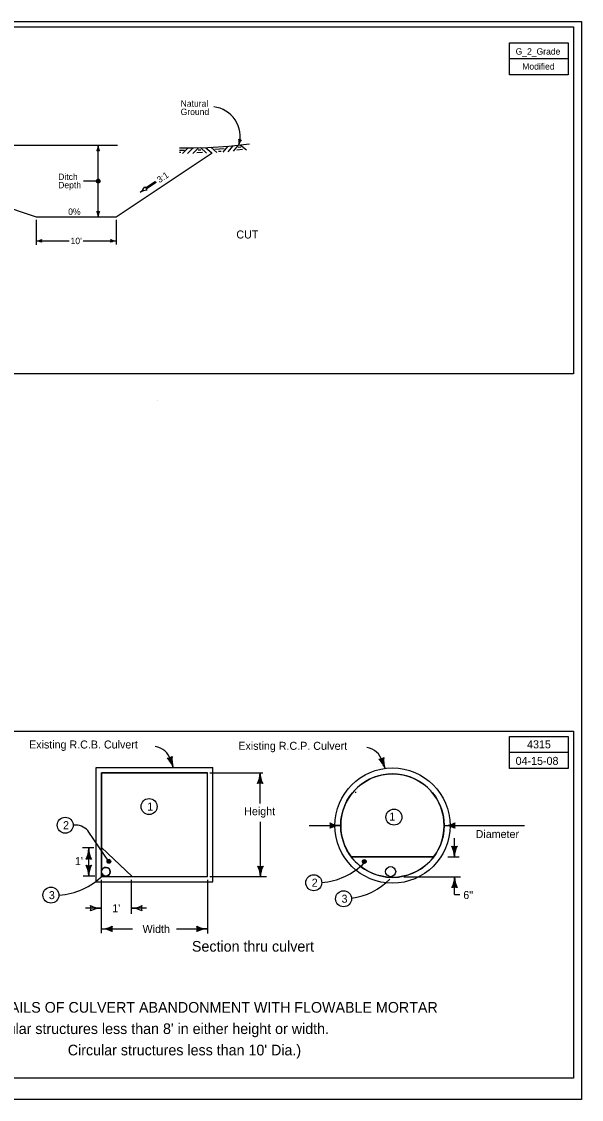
# Model space of a CAD drawing. Extents: x 10133 to 81668, y 7924 to 11018.
# Drawn here: x 12218 to 13268, y 7924 to 9944 of the extents above; entities that cross this region are included whole.
import ezdxf

# ---------------------------------------------------------------- set-up
doc = ezdxf.new("R2010")
doc.units = 0
for name, color, linetype in [('dsnCellElements', 7, 'Continuous'), ('DsnShtMinorGrid06', 7, 'Continuous'), ('DsnShtMinorGrid08', 7, 'Continuous'), ('DsnShtMinorGrid09', 7, 'Continuous'), ('DsnShtMinorGrid10', 7, 'Continuous'), ('DsnShtMinorGrid11', 7, 'Continuous'), ('dsnStdNameDate', 7, 'Continuous'), ('Level 12', 7, 'Continuous'), ('SheetBorder', 7, 'Continuous'), ('ShtPlotIdentification', 7, 'Continuous')]:
    doc.layers.add(name, color=color, linetype=linetype)

msp = doc.modelspace()

# ---------------------------------------------------------------- linework, layer by layer
at = {"layer": 'dsnCellElements'}
for p, q in [((12357.4, 8331.9), (12357.4, 8546.4)), ((12357.4, 8546.4), (12576.1, 8546.4)), ((12502.1, 8546.4), (12495.6, 8564.5)), ((12576.1, 8331.9), (12576.1, 8546.4)), ((12899.2, 8544.3), (12892.6, 8562.4)), ((12367.5, 8342), (12367.5, 8536.3)), ((12367.5, 8536.3), (12566, 8536.3)), ((12566, 8342), (12566, 8536.3)), ((12570.5, 8536), (12670.1, 8536)), ((12664.9, 8478.4), (12664.9, 8536)), ((12664.9, 8536), (12664.9, 8516.8)), ((12665.5, 8341.7), (12665.5, 8444)), ((12319.2, 8438), (12314.4, 8438)), ((12381.3, 8370.2), (12344, 8424.9)), ((12757.2, 8437.2), (12816.1, 8437.2)), ((12816.1, 8437.2), (12796.9, 8437.2)), ((13010.1, 8437.2), (13160.6, 8437.2)), ((13010.1, 8437.2), (13029.3, 8437.2)), ((13029.5, 8378.1), (13029.5, 8413.7)), ((12332.1, 8396.1), (12353.2, 8396.1)), ((12343.7, 8394), (12343.7, 8374.8)), ((12343.7, 8342.9), (12343.7, 8394)), ((12367.5, 8395.9), (12424.7, 8342)), ((13029.4, 8378.6), (13029.4, 8397.8)), ((12836, 8378.4), (12984.5, 8378.4)), ((13016.9, 8378.4), (13038, 8378.4)), ((12333.2, 8342.9), (12354.7, 8342.9)), ((12343.7, 8342.9), (12343.7, 8362.1)), ((12665.6, 8341.3), (12665.6, 8360.5)), ((12357.4, 8331.9), (12576.1, 8331.9)), ((12367.5, 8342), (12566, 8342)), ((12367.5, 8235.9), (12367.5, 8335.8)), ((12423.8, 8271.6), (12423.8, 8335.8)), ((12566.8, 8234.9), (12566.8, 8335.8)), ((12570.5, 8341.6), (12676.9, 8341.6)), ((12934.4, 8341.2), (13040.9, 8341.2)), ((13029.5, 8307.8), (13029.5, 8341.2)), ((13029.6, 8340.9), (13029.6, 8321.7)), ((13029.5, 8307.8), (13039.5, 8307.8)), ((12367.3, 8282.2), (12337.4, 8282.2)), ((12452, 8282.2), (12423.3, 8282.2)), ((12367.5, 8243.6), (12386.7, 8243.6)), ((12367.5, 8243.6), (12425.5, 8243.6)), ((12508.4, 8243.6), (12566.5, 8243.6)), ((12566.5, 8243.6), (12547.3, 8243.6))]:
    msp.add_line(p, q, dxfattribs=at)
for points in [[(12499, 8565.3), (12495.9, 8563.4), (12492.3, 8562.9), (12495.7, 8559.5), (12499.5, 8553.7), (12498.6, 8561.1), (12498.8, 8564.6), (12496.2, 8562.8), (12493.9, 8562.3), (12496.1, 8560.1), (12498.3, 8556.9), (12498, 8561), (12498, 8563.3), (12495.2, 8561.8), (12497.3, 8559.6), (12497.2, 8561.9), (12496.2, 8561.6), (12496.9, 8560.7)], [(12896.1, 8563.2), (12893, 8561.3), (12889.4, 8560.8), (12892.8, 8557.5), (12896.5, 8551.6), (12895.6, 8559), (12895.9, 8562.5), (12893.2, 8560.7), (12890.9, 8560.2), (12893.2, 8558), (12895.4, 8554.8), (12895.1, 8558.9), (12895.1, 8561.2), (12892.3, 8559.8), (12894.4, 8557.5), (12894.3, 8559.8), (12893.3, 8559.5), (12893.9, 8558.6)], [(12661.4, 8517.2), (12665, 8517.9), (12668.6, 8517.1), (12666.5, 8521.4), (12665, 8528.3), (12663.2, 8520.9), (12661.8, 8517.8), (12665, 8518.6), (12667.3, 8518.3), (12665.9, 8521.1), (12665, 8524.9), (12663.8, 8520.8), (12663.1, 8518.7), (12666.1, 8519.1), (12665, 8521.9), (12664.3, 8519.7), (12665.3, 8519.7), (12665, 8520.7)], [(12843, 8498.6), (12844.8, 8500.4)], [(12797.3, 8440.8), (12798, 8437.2), (12797.2, 8433.6), (12801.5, 8435.7), (12808.4, 8437.2), (12801, 8438.9), (12797.9, 8440.3), (12798.6, 8437.2), (12798.3, 8434.9), (12801.2, 8436.2), (12805, 8437.2), (12800.9, 8438.4), (12798.8, 8439.1), (12799.2, 8436), (12802, 8437.2), (12799.8, 8437.9), (12799.8, 8436.8), (12800.8, 8437.2)], [(13028.9, 8433.6), (13028.2, 8437.2), (13028.9, 8440.8), (13024.6, 8438.8), (13017.8, 8437.2), (13025.2, 8435.5), (13028.3, 8434.1), (13027.5, 8437.2), (13027.8, 8439.5), (13025, 8438.2), (13021.2, 8437.2), (13025.3, 8436), (13027.4, 8435.3), (13027, 8438.4), (13024.2, 8437.2), (13026.4, 8436.5), (13026.4, 8437.6), (13025.4, 8437.2)], [(12340.2, 8375.2), (12343.7, 8375.9), (12347.3, 8375.2), (12345.3, 8379.5), (12343.7, 8386.3), (12342, 8379), (12340.6, 8375.8), (12343.7, 8376.6), (12346, 8376.3), (12344.7, 8379.1), (12343.7, 8382.9), (12342.6, 8378.9), (12341.8, 8376.8), (12344.9, 8377.2), (12343.7, 8380), (12343, 8377.8), (12344.1, 8377.7), (12343.8, 8378.8)], [(13033, 8397.4), (13029.4, 8396.7), (13025.8, 8397.4), (13027.9, 8393.1), (13029.4, 8386.3), (13031.1, 8393.6), (13032.5, 8396.8), (13029.4, 8396), (13027.1, 8396.3), (13028.4, 8393.5), (13029.4, 8389.7), (13030.6, 8393.7), (13031.3, 8395.8), (13028.2, 8395.4), (13029.4, 8392.6), (13030.1, 8394.8), (13029, 8394.9), (13029.4, 8393.8)], [(12381.6, 8373.4), (12380.4, 8372.8), (12378.6, 8372.3), (12378.2, 8370.4), (12378.5, 8368.8), (12379.7, 8367.3), (12381.4, 8367.4), (12383.3, 8367.7), (12384.1, 8369.1), (12384.3, 8370.7), (12383.2, 8372.7), (12381.9, 8372.9), (12380, 8372.4), (12378.5, 8371.2), (12378.6, 8369.5), (12379.7, 8368.1), (12381.4, 8367.9), (12383.2, 8368.3), (12383.5, 8369.3), (12383.9, 8370.6), (12383, 8372.1), (12381.7, 8372.1), (12380.2, 8371.8), (12379, 8370.9), (12379.6, 8369.4), (12380.8, 8368.5), (12382.3, 8368.5), (12382.7, 8369.3), (12383.2, 8370.2), (12382.4, 8371.5), (12381.3, 8371.7), (12380.3, 8371.2), (12380.2, 8370.1), (12380.7, 8369.2), (12381.8, 8369), (12382.3, 8369.4), (12382.6, 8370), (12382, 8370.9), (12381.3, 8371.1), (12380.6, 8370.7), (12380.7, 8370.1), (12381.2, 8369.7), (12382, 8369.7), (12382, 8370.2), (12381.3, 8370.5)], [(12833, 8382.5), (12833, 8382.5)], [(12860.6, 8373), (12859.4, 8372.5), (12857.5, 8371.9), (12857.2, 8370), (12857.4, 8368.4), (12858.6, 8366.9), (12860.4, 8367), (12862.2, 8367.3), (12863.1, 8368.8), (12863.3, 8370.3), (12862.2, 8372.3), (12860.8, 8372.5), (12859, 8372), (12857.5, 8370.9), (12857.5, 8369.1), (12858.7, 8367.7), (12860.3, 8367.5), (12862.2, 8367.9), (12862.5, 8368.9), (12862.8, 8370.2), (12862, 8371.7), (12860.6, 8371.7), (12859.1, 8371.4), (12858, 8370.6), (12858.6, 8369), (12859.7, 8368.1), (12861.3, 8368.1), (12861.6, 8368.9), (12862.1, 8369.9), (12861.4, 8371.1), (12860.2, 8371.4), (12859.2, 8370.8), (12859.2, 8369.7), (12859.7, 8368.9), (12860.7, 8368.6), (12861.2, 8369), (12861.5, 8369.6), (12861, 8370.5), (12860.3, 8370.7), (12859.5, 8370.3), (12859.7, 8369.7), (12860.2, 8369.3), (12860.9, 8369.3), (12860.9, 8369.8), (12860.3, 8370.1)], [(12347.3, 8361.7), (12343.7, 8361), (12340.1, 8361.8), (12342.2, 8357.5), (12343.7, 8350.6), (12345.4, 8358), (12346.8, 8361.1), (12343.7, 8360.4), (12341.4, 8360.7), (12342.7, 8357.8), (12343.7, 8354), (12344.9, 8358.1), (12345.6, 8360.2), (12342.5, 8359.8), (12343.7, 8357), (12344.4, 8359.2), (12343.3, 8359.2), (12343.7, 8358.2)], [(12669.1, 8360.2), (12665.6, 8359.4), (12662, 8360.2), (12664, 8355.9), (12665.6, 8349.1), (12667.3, 8356.4), (12668.7, 8359.6), (12665.6, 8358.8), (12663.3, 8359.1), (12664.6, 8356.2), (12665.6, 8352.5), (12666.7, 8356.5), (12667.5, 8358.6), (12664.4, 8358.2), (12665.6, 8355.4), (12666.3, 8357.6), (12665.2, 8357.6), (12665.5, 8356.6)], [(13026, 8322.1), (13029.6, 8322.8), (13033.2, 8322), (13031.1, 8326.3), (13029.6, 8333.2), (13027.9, 8325.8), (13026.5, 8322.7), (13029.6, 8323.4), (13031.9, 8323.1), (13030.6, 8326), (13029.6, 8329.8), (13028.4, 8325.7), (13027.7, 8323.6), (13030.8, 8324), (13029.6, 8326.8), (13028.9, 8324.6), (13030, 8324.6), (13029.6, 8325.6)], [(12386.3, 8240), (12385.6, 8243.6), (12386.3, 8247.2), (12382, 8245.1), (12375.2, 8243.6), (12382.5, 8241.9), (12385.7, 8240.5), (12384.9, 8243.6), (12385.2, 8245.9), (12382.4, 8244.6), (12378.6, 8243.6), (12382.6, 8242.4), (12384.7, 8241.7), (12384.3, 8244.8), (12381.5, 8243.6), (12383.7, 8242.9), (12383.8, 8244), (12382.7, 8243.6)], [(12547.7, 8247.1), (12548.4, 8243.6), (12547.7, 8240), (12552, 8242), (12558.8, 8243.6), (12551.4, 8245.3), (12548.3, 8246.7), (12549.1, 8243.6), (12548.8, 8241.3), (12551.6, 8242.6), (12555.4, 8243.6), (12551.4, 8244.7), (12549.3, 8245.5), (12549.6, 8242.4), (12552.4, 8243.6), (12550.2, 8244.3), (12550.2, 8243.2), (12551.2, 8243.5)]]:
    msp.add_lwpolyline(points, dxfattribs=at)
for centre, radius in [((12913.1, 8437.2), 108), ((12913.1, 8437.2), 97), ((12456.7, 8472.9), 15), ((12915.9, 8453.1), 15), ((12299.4, 8438), 15), ((12381.3, 8370.2), 3.5), ((12860.3, 8369.8), 3.5), ((12375.6, 8350.7), 8.23), ((12765.6, 8330.2), 15), ((12909.7, 8350.9), 9.51), ((12272.7, 8306.9), 15), ((12821.5, 8300.1), 15)]:
    msp.add_circle(centre, radius, dxfattribs=at)
for centre, radius, start, end in [((12461.9, 8549.3), 36.9, 17.6823, 79.9899), ((12489.9, 8579.9), 16.4, 272.2666, 307.7334), ((12542.1, 8560.9), 42.5, 171.9275, 200), ((12858.9, 8547.2), 36.9, 17.6823, 79.9899), ((12462.2, 8531.9), 42.5, 20, 48.0725), ((12887, 8577.8), 16.4, 272.2666, 307.7334), ((12859.3, 8529.8), 42.5, 20, 48.0725), ((12939.1, 8558.8), 42.5, 171.9275, 200), ((12622.4, 8536), 42.5, 331.9275, 0), ((12707.4, 8536), 42.5, 180, 208.0725), ((12664.9, 8500.4), 16.4, 72.2666, 107.7334), ((12319.2, 8408), 30, 34.2688, 90), ((12780.5, 8437.2), 16.4, 342.2666, 17.7334), ((12816.1, 8479.7), 42.5, 241.9275, 270), ((12816.1, 8394.7), 42.5, 90, 118.0725), ((13010.1, 8479.7), 42.5, 270, 298.0725), ((13010.1, 8394.7), 42.5, 61.9275, 90), ((13045.7, 8437.2), 16.4, 162.2666, 197.7334), ((12301.2, 8394), 42.5, 331.9275, 0), ((12386.2, 8394), 42.5, 180, 208.0725), ((13029.4, 8414.2), 16.4, 252.2666, 287.7333), ((12986.9, 8378.6), 42.5, 0, 28.0725), ((13071.9, 8378.6), 42.5, 151.9275, 180), ((12343.7, 8358.4), 16.4, 72.2666, 107.7334), ((12343.7, 8378.5), 16.4, 252.2666, 287.7333), ((12301.2, 8342.9), 42.5, 0, 28.0725), ((12386.2, 8342.9), 42.5, 151.9275, 180), ((12769.6, 8458.8), 128.8, 274.9104, 314.6972), ((12279.4, 8435.5), 128.8, 273.6929, 314.6972), ((12665.6, 8377), 16.4, 252.2666, 287.7333), ((12623.1, 8341.3), 42.5, 0, 28.0725), ((12708.1, 8341.3), 42.5, 151.9275, 180), ((12817.9, 8428.4), 128.8, 278.3054, 314.6972), ((12987.1, 8340.9), 42.5, 331.9275, 0), ((13072.1, 8340.9), 42.5, 180, 208.0725), ((13029.6, 8305.3), 16.4, 72.2666, 107.7334), ((12331.5, 8282.2), 16.4, 342.2666, 17.7333), ((12367.1, 8324.7), 42.5, 241.9275, 270), ((12367.1, 8239.7), 42.5, 90, 118.0725), ((12423.3, 8324.7), 42.5, 270, 298.0725), ((12423.3, 8239.7), 42.5, 61.9275, 90), ((12458.9, 8282.2), 16.4, 162.2666, 197.7334), ((12367.5, 8286.1), 42.5, 270, 298.0725), ((12367.5, 8201.1), 42.5, 61.9275, 90), ((12403.1, 8243.6), 16.4, 162.2666, 197.7334), ((12530.9, 8243.6), 16.4, 342.2666, 17.7333), ((12566.5, 8286.1), 42.5, 241.9275, 270), ((12566.5, 8201.1), 42.5, 90, 118.0725)]:
    msp.add_arc(centre, radius, start, end, dxfattribs=at)
at = {"layer": 'DsnShtMinorGrid06'}
for p, q in [((12397.7, 9711.5), (11691.5, 9711.5)), ((12361.3, 9578.2), (12361.3, 9707.6)), ((12361.3, 9645), (12333.8, 9645)), ((12245, 9572.2), (12245, 9525.3)), ((12395, 9572.2), (12395, 9526.1)), ((12245, 9532.9), (12307, 9532.9)), ((12333, 9532.9), (12395, 9532.9))]:
    msp.add_line(p, q, dxfattribs=at)
msp.add_lwpolyline([(12361, 9641.8), (12362.2, 9642.3), (12364, 9642.9), (12364.4, 9644.8), (12364.1, 9646.4), (12363, 9647.9), (12361.2, 9647.8), (12359.4, 9647.5), (12358.5, 9646), (12358.3, 9644.5), (12359.4, 9642.5), (12360.7, 9642.3), (12362.6, 9642.8), (12364.1, 9643.9), (12364, 9645.7), (12362.9, 9647.1), (12361.2, 9647.2), (12359.4, 9646.9), (12359.1, 9645.8), (12358.7, 9644.6), (12359.6, 9643.1), (12360.9, 9643.1), (12362.5, 9643.4), (12363.6, 9644.2), (12363, 9645.7), (12361.9, 9646.6), (12360.3, 9646.7), (12359.9, 9645.9), (12359.4, 9644.9), (12360.2, 9643.7), (12361.3, 9643.4), (12362.3, 9644), (12362.4, 9645.1), (12361.9, 9645.9), (12360.8, 9646.2), (12360.3, 9645.8), (12360, 9645.1), (12360.6, 9644.2), (12361.3, 9644.1), (12362, 9644.5), (12361.9, 9645.1), (12361.4, 9645.5), (12360.7, 9645.5), (12360.7, 9645), (12361.3, 9644.7)], dxfattribs=at)
msp.add_circle((12361.3, 9645), 3.5, dxfattribs=at)
for centre, radius, start, end in [((12340, 9711.5), 21.3, 331.9275, 0), ((12361.3, 9693.7), 8.21, 72.2666, 107.7334), ((12382.5, 9711.5), 21.3, 180, 208.0725), ((12361.3, 9596), 8.21, 252.2666, 287.7334), ((12340, 9578.2), 21.3, 0, 28.0725), ((12382.5, 9578.2), 21.3, 151.9275, 180), ((12245, 9554.1), 21.3, 270, 298.0725), ((12262.8, 9532.9), 8.21, 162.2666, 197.7334), ((12377.2, 9532.9), 8.21, 342.2666, 17.7334), ((12395, 9554.1), 21.3, 241.9275, 270), ((12245, 9511.6), 21.3, 61.9275, 90), ((12395, 9511.6), 21.3, 90, 118.0725)]:
    msp.add_arc(centre, radius, start, end, dxfattribs=at)
at = {"layer": 'DsnShtMinorGrid08'}
for points in [[(10147.5, 9934), (13252.5, 9934), (13252.5, 9284), (10147.5, 9284), (10147.5, 9934)], [(13242.5, 9904), (13242.5, 9844), (13132.5, 9844), (13132.5, 9904), (13242.5, 9904), (13242.5, 9874), (13132.5, 9874)]]:
    msp.add_lwpolyline(points, dxfattribs=at)
at = {"layer": 'DsnShtMinorGrid09'}
for p, q in [((12450.1, 9632.2), (12468.4, 9644.4)), ((12469.7, 9642.4), (12451.4, 9630.2)), ((12468.4, 9644.4), (12469.7, 9642.4)), ((12440.1, 9624.1), (12440.1, 9624.1)), ((12448.5, 9634.5), (12450.1, 9632.2)), ((12451.4, 9630.2), (12452.9, 9627.9))]:
    msp.add_line(p, q, dxfattribs=at)
for centre, radius, start, end in [((12571.4, 9728.6), 56, 343.9435, 83.3835), ((12628.7, 9730.6), 8.21, 241.2344, 276.7011), ((12604.4, 9717.2), 21.3, 348.9677, 17.0402), ((12646.1, 9709), 21.3, 140.8953, 168.9677), ((12424.9, 9645), 25.8, 306.0394, 336.0695), ((12453.5, 9602.1), 25.8, 91.3054, 121.3354)]:
    msp.add_arc(centre, radius, start, end, dxfattribs=at)
at = {"layer": 'DsnShtMinorGrid10'}
for p, q in [((12395, 9578.2), (12574.7, 9698)), ((11977.5, 9667.4), (12245, 9578.2)), ((12245, 9578.2), (12395, 9578.2))]:
    msp.add_line(p, q, dxfattribs=at)
at = {"layer": 'DsnShtMinorGrid11'}
for p, q in [((12530.2, 9707.3), (12519.5, 9696.8)), ((12539.5, 9707.1), (12528.8, 9696.6)), ((12549.3, 9707.5), (12539, 9696.6)), ((12553.3, 9707.7), (12564.2, 9697.4)), ((12563.1, 9707.6), (12574.4, 9697.8)), ((12572.4, 9708.4), (12583.7, 9698.6)), ((12604.7, 9710.6), (12594.9, 9699.3)), ((12614, 9711.4), (12604.6, 9699.7)), ((12623.7, 9712.6), (12614.3, 9700.9)), ((12627.8, 9713.1), (12639.4, 9703.7))]:
    msp.add_line(p, q, dxfattribs=at)
for points in [[(12513.9, 9703.3), (12523, 9703.3)], [(12513.9, 9699), (12516.4, 9699)], [(12514, 9707.4), (12540.5, 9707.3), (12567, 9708.1), (12606.1, 9710.7), (12645, 9714.9)], [(12546.2, 9698.9), (12556.9, 9699.2)], [(12549, 9703.4), (12553.9, 9703.5)], [(12579.8, 9704.8), (12597.8, 9706)], [(12586.7, 9700.9), (12591.6, 9701.3)], [(12621.4, 9703.8), (12631.9, 9705)], [(12623.7, 9708.5), (12628.6, 9709)]]:
    msp.add_lwpolyline(points, dxfattribs=at)
at = {"layer": 'Level 12'}
for p, q in [((12990.2, 8378.4), (12836, 8378.4)), ((12836, 8378.4), (12990.2, 8378.4))]:
    msp.add_line(p, q, dxfattribs=at)
for points in [[(10147.5, 8614), (13252.5, 8614), (13252.5, 7964), (10147.5, 7964), (10147.5, 8614)], [(13242.5, 8604), (13242.5, 8544), (13132.5, 8544), (13132.5, 8604), (13242.5, 8604), (13242.5, 8574), (13132.5, 8574)], [(12367.5, 8349.5), (12367.5, 8342), (12424.7, 8342), (12367.5, 8395.9), (12367.5, 8351.9)]]:
    msp.add_lwpolyline(points, dxfattribs=at)
msp.add_lwpolyline([(12566, 8342), (12566, 8536.3), (12367.5, 8536.3), (12367.5, 8395.9), (12424.7, 8342)], close=True, dxfattribs=at)
for centre, radius in [((12456.7, 8472.9), 15), ((12915.9, 8453.1), 15), ((12381.3, 8370.2), 3.5), ((12860.3, 8369.8), 3.5), ((12909.7, 8350.9), 9.51)]:
    msp.add_circle(centre, radius, dxfattribs=at)
for centre, radius, start, end in [((12913.1, 8437.2), 97, 322.6702, 217.3298), ((12913.1, 8437.2), 97, 217.3298, 322.6702), ((12375.6, 8350.7), 8.23, 188.3205, 171.6795)]:
    msp.add_arc(centre, radius, start, end, dxfattribs=at)
at = {"layer": 'SheetBorder'}
msp.add_lwpolyline([(10132.5, 9944), (13267.5, 9944), (13267.5, 7924), (10132.5, 7924)], close=True, dxfattribs=at)
at = {"layer": 'ShtPlotIdentification'}
for p, q in [((12472.5, 9234), (12472.5, 9234)), ((13252.5, 8614), (13252.5, 8614)), ((12984.5, 8378.4), (12990.5, 8378.4))]:
    msp.add_line(p, q, dxfattribs=at)

# ---------------------------------------------------------------- texts
at = {"layer": 'DsnShtMinorGrid06'}
for s, p in [('Ditch', (12286.3, 9647.1)), ('Depth', (12286.3, 9631.6)), ('0%', (12305, 9581.7)), ("10'", (12309.5, 9526.9))]:
    msp.add_text(s, height=12, dxfattribs=at).set_placement(p)
at = {"layer": 'DsnShtMinorGrid09'}
for s, p in [('Ground', (12515.9, 9768.8)), ('Natural', (12515.9, 9784.4))]:
    msp.add_text(s, height=12, dxfattribs=at).set_placement(p)
for s, height, rotation, p in [('3:1', 12, 33.6874, (12476.3, 9641)), ('CUT', 15, 359.9585, (12620.4, 9537.5))]:
    msp.add_text(s, height=height, rotation=rotation, dxfattribs=at).set_placement(p)
at = {"layer": 'dsnStdNameDate'}
for s, height, p in [('G_2_Grade', 12, (13144.1, 9882)), ('Modified', 12, (13156.5, 9854)), ('4315', 15, (13165.6, 8582)), ('04-15-08', 15, (13144.1, 8551))]:
    msp.add_text(s, height=height, dxfattribs=at).set_placement(p)
at = {"layer": 'ShtPlotIdentification'}
for s, height, p in [('Existing R.C.B. Culvert', 15, (12231.6, 8581.7)), ('Existing R.C.P. Culvert', 15, (12624.1, 8579.2)), ('1', 15, (12453.3, 8465.4)), ('Height', 15, (12635.1, 8456.7)), ('2', 15, (12295.4, 8430.5)), ('1', 15, (12907.1, 8446.5)), ('Diameter', 15, (13069.1, 8413.9)), ("1'", 15, (12317.7, 8363.1)), ('2', 15, (12761.7, 8322.7)), ('3', 15, (12268.8, 8299.4)), ('3', 15, (12817.6, 8292.6)), ('6"', 15, (13046, 8299.6)), ("1'", 15, (12387.7, 8274.7)), ('Width', 15, (12444.5, 8236)), ('DETAILS OF CULVERT ABANDONMENT WITH FLOWABLE MORTAR ', 20, (12142.1, 8086.6)), ("(Rectangular structures less than 8' in either height or width. ", 20, (12082.9, 8046.6)), ("Circular structures less than 10' Dia.) ", 20, (12304.2, 8006.6))]:
    msp.add_text(s, height=height, dxfattribs=at).set_placement(p)
msp.add_text('Section thru culvert', height=20, rotation=359.9816, dxfattribs=at).set_placement((12537.1, 8201))

doc.saveas('drawing.dxf')
